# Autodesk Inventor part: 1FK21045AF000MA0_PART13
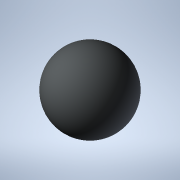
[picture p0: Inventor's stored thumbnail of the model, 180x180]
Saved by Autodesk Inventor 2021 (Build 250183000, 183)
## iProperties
Created: 2025-04
Part Number: 1FK21045AF000MA0_PART13
Material: Generic
Catalog Web Link: www.3dfindit.com
Description: -Servo synchronous motor
Document SubType Name: Modeling
Designer: psAdmin
Mass: 0.137258 g
Surface Area: 1.2868 cm^2
Volume: 0.137258 cm^3
Density: 1 g/cm^3
Appearance: PSOLRGB-212-217-219
Category: PARTsolutions
Title: 1FK21045AF000MA0_PART13
Author: Cadenas PARTsolutions
Comments: Servo synchronous motor
Sending System: PARTsolutions
Preprocessor: ST-DEVELOPER v19.3
PSOL_IDENT_0: {$CADENAS_DATA/23d-libs/siemens_ag/_cat_/8b/0a/1fk21045af000ma0.prj},216 {VTYP=3D},{NB=1FK21045AF000
PSOL_IDENT_1: MA0_PART13},{LINA=1FK21045AF000MA0_PART13},{NN=1FK21045AF000MA0_PART13},{NOPRJ=TRUE},{DATE=19.08.202
PSOL_IDENT_2: 5 14:00:48},{GEOMDATE=30.07.2025 02:00:28},{VERSION=},{LINEID=10},{WBVAR=},{WBNUMERIC=}  {NB=1FK2104
PSOL_IDENT_3: 5AF000MA0_PART13},{LINA=1FK21045AF000MA0_PART13},{KT=DUMMY},{PREVIEW=../../../_pool_/a9/69/p_d211_xx
PSOL_IDENT_4: _00818j.png},{DESCSHORT=SIMOTICS S-1FK2 HD, SINAMICS S210 3AC 400V-480V, 2.4 Nm, 3000 rpm},{DESCLONG=
PSOL_IDENT_5: SIMOTICS S-1FK2 HD servo motor M0=2.4 Nm; PN = 0.75 kW at nN=3000 rpm (380-480 V); PN = 0.375 kW at
PSOL_IDENT_6: nN=1500 rpm (200-240 V); degree of protection IP64; cylindrical shaft D19x40mm; absolute encoder 22-
PSOL_IDENT_7: bit + 12-bit multiturn (encoder AM22DQC); with OCC interface; plug size M17, rotatable; SIMOTICS S-1
PSOL_IDENT_8: FK2 servomotorfor a wide range of uses in industrial environments. SIMOTICS S‑1FK2 servomotors are c
PSOL_IDENT_9: ompact synchronous motors with a high dynamic performance that set themselves apart as a result of t
PSOL_IDENT_10: heir high power density, degree of protection and overload capability. The motors are available in t
PSOL_IDENT_11: wo variants: as High Dynamic variant (highest dynamic performance as a result of the low intrinsic m
PSOL_IDENT_12: oment of inertia for applications demanding a high dynamic performance with low moved masses) - and
PSOL_IDENT_13: as Compact variant (precise and stable closed-loop control for medium up to large moved masses as a
PSOL_IDENT_14: result of a medium intrinsic moment of inertia). SIMOTICSS‑1FK2 servomotors fully exploit their stre
PSOL_IDENT_15: ngths in a system with the SINAMICSS210 frequency converter and simple connection using the one cabl
PSOL_IDENT_16: e connection (OCC). Advantages include the short control and positioning times, fast and precise cor
PSOL_IDENT_17: rection of disturbing quantities as well as stable control with a high dynamic performance. The serv
PSOL_IDENT_18: o motors can be configured to address a wide range of requirements. For example with and without hol
PSOL_IDENT_19: ding brake, IP64 or IP65 degree of protection, singleturn or multiturn absolute encoders - to name j
PSOL_IDENT_20: ust a few. Further, the servomotors are available in different shaft heights extending from 20 to 10
PSOL_IDENT_21: 0. A shaft sealing ring is available to achieve an IP65 degree of protection and for subsequent moun
PSOL_IDENT_22: ting at the motor or as spare part. SIMOTICS - the optimum motor for each and every motion control a
PSOL_IDENT_23: pplication.},{INTNO=195125050112},{SUPPLIERALTNO=1FK2104-5AF00-0MA0},{MANUID=1FK21045AF000MA0},{MANU
PSOL_IDENT_24: NAME=Siemens},{MANUTYPEDESC=Synchronous motor 1FK2-HD 2.4 NM},{AAU732=SIMOTICS},{AAO057=S-1FK2},{AAU
PSOL_IDENT_25: 734=SIMOTICS S-1FK2 HD servo motor M0=2.4 Nm; PN = 0.75 kW at nN=3000 rpm (380-480 V); PN = 0.375 kW
PSOL_IDENT_26: at nN=1500 rpm (200-240 V); degree of protection IP64; cylindrical shaft D19x40mm; absolute encoder
PSOL_IDENT_27: 22-bit + 12-bit multiturn (encoder AM22DQC); with OCC interface; plug size M17, rotatable;},{AAW338=
PSOL_IDENT_28: Synchronous motor 1FK2-HD 2.4 NM},{AAO742=SIMOTICS},{AAO663=4042948692912},{NOCUPEROU=1},{PRICEQUANT
PSOL_IDENT_29: ITY=1},{QUANTITYMIN=1},{QUANTITYINT=1},{CTN=85015100},{COO=DE},{AAO676=1FK2104-5AF00-0MA0},{AAO677=S
PSOL_IDENT_30: iemens AG},{ORDERUNIT=C62},{CONTENTUNIT=C62}
NB: 1FK21045AF000MA0_PART13
NT: Servo synchronous motor
NBSYN: $MANUID._PART13
LINA: 1FK21045AF000MA0_PART13
CATALOG: SIEMENS
PREVIEW: ../../../_pool_/a9/69/p_d211_xx_00818j.png
DESCSHORT: SIMOTICS S-1FK2 HD, SINAMICS S210 3AC 400V-480V, 2.4 Nm, 3000 rpm
DESCLONG: SIMOTICS S-1FK2 HD servo motor M0=2.4 Nm; PN = 0.75 kW at nN=3000 rpm (380-480 V); PN = 0.375 kW at nN=1500 rpm (200-240 V); degree of protection IP64; cylindri
INTNO: 195125050112
SUPPLIERALTNO: 1FK2104-5AF00-0MA0
MANUID: 1FK21045AF000MA0
MANUNAME: Siemens
MANUTYPEDESC: Synchronous motor 1FK2-HD 2.4 NM
AAU732: SIMOTICS
AAO057: S-1FK2
AAU734: SIMOTICS S-1FK2 HD servo motor M0=2.4 Nm; PN = 0.75 kW at nN=3000 rpm (380-480 V); PN = 0.375 kW at nN=1500 rpm (200-240 V); degree of protection IP64; cylindri
AAW338: Synchronous motor 1FK2-HD 2.4 NM
AAO742: SIMOTICS
AAO663: 4042948692912.0
NOCUPEROU: 1
PRICEQUANTITY: 1
QUANTITYMIN: 1
QUANTITYINT: 1
CTN: 85015100
COO: DE
ARTICLENO: 1FK21045AF000MA0_PART13
BOMINFO: 1FK21045AF000MA0_PART13
CREATOR: CADENAS GmbH
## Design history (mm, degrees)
feature "2025_04_17_15_40_42_0766"
body "Solid1"
